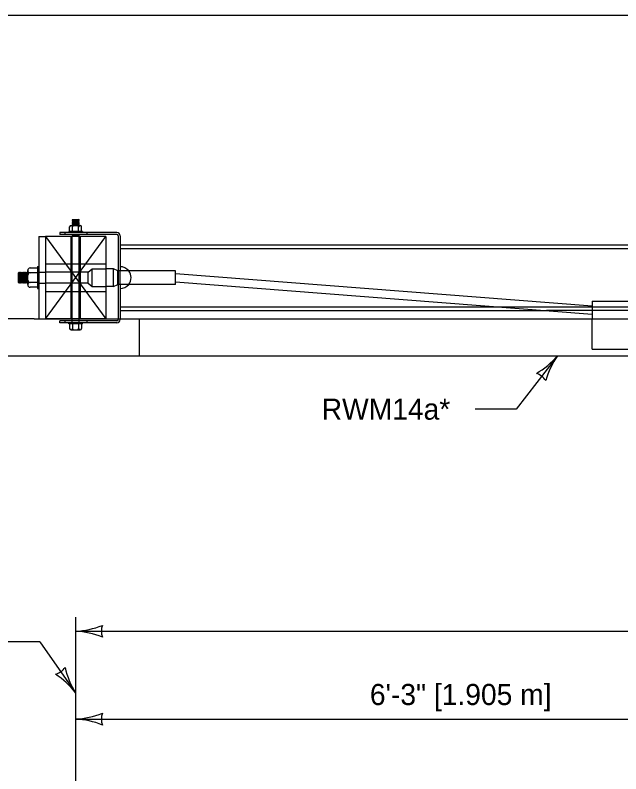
# Model space of a CAD drawing. Extents: x 49991.4 to 50021, y 49987.6 to 50011.4.
# Drawn here: x 50001.173 to 50002.896, y 49996.841 to 49998.999 of the extents above; entities that cross this region are included whole.
import ezdxf

# ---------------------------------------------------------------- set-up
doc = ezdxf.new("R2010")
doc.units = 0
for name, color, linetype in [('Level 1', 7, 'Continuous'), ('Level 2', 7, 'Continuous'), ('Level 3', 7, 'Continuous'), ('Level 4', 7, 'Continuous')]:
    doc.layers.add(name, color=color, linetype=linetype)

msp = doc.modelspace()

# ---------------------------------------------------------------- linework, layer by layer
at = {"layer": 'Level 1'}
for p, q in [((50001.3538, 49998.4176), (50001.3355, 49998.4166)), ((50001.3355, 49998.4166), (50001.3367, 49998.4176)), ((50001.3355, 49998.4166), (50001.3367, 49998.4156)), ((50001.3538, 49998.4156), (50001.3355, 49998.4147)), ((50001.3355, 49998.4147), (50001.3367, 49998.4156)), ((50001.3355, 49998.4147), (50001.3367, 49998.4137)), ((50001.3538, 49998.4137), (50001.3355, 49998.4128)), ((50001.3355, 49998.4128), (50001.3367, 49998.4137)), ((50001.3355, 49998.4128), (50001.3367, 49998.4118)), ((50001.3538, 49998.4118), (50001.3355, 49998.4109)), ((50001.3355, 49998.4109), (50001.3367, 49998.4118)), ((50001.3355, 49998.4109), (50001.3367, 49998.4099)), ((50001.3367, 49998.4176), (50001.3538, 49998.4176)), ((50001.355, 49998.4166), (50001.3367, 49998.4156)), ((50001.355, 49998.4147), (50001.3367, 49998.4137)), ((50001.355, 49998.4128), (50001.3367, 49998.4118)), ((50001.355, 49998.4109), (50001.3367, 49998.4099)), ((50001.3538, 49998.4176), (50001.355, 49998.4166)), ((50001.3538, 49998.4156), (50001.355, 49998.4166)), ((50001.3538, 49998.4156), (50001.355, 49998.4147)), ((50001.3538, 49998.4137), (50001.355, 49998.4147)), ((50001.3538, 49998.4137), (50001.355, 49998.4128)), ((50001.3538, 49998.4118), (50001.355, 49998.4128)), ((50001.3538, 49998.4118), (50001.355, 49998.4109)), ((50001.3538, 49998.4099), (50001.355, 49998.4109)), ((50001.3282, 49998.384), (50001.3282, 49998.3969)), ((50001.3324, 49998.401), (50001.3581, 49998.401)), ((50001.3538, 49998.4099), (50001.3355, 49998.409)), ((50001.3355, 49998.409), (50001.3367, 49998.4099)), ((50001.3355, 49998.409), (50001.3367, 49998.408)), ((50001.3538, 49998.408), (50001.3355, 49998.407)), ((50001.3355, 49998.407), (50001.3367, 49998.408)), ((50001.3355, 49998.407), (50001.3367, 49998.406)), ((50001.3538, 49998.406), (50001.3355, 49998.4051)), ((50001.3355, 49998.4051), (50001.3367, 49998.406)), ((50001.3355, 49998.4051), (50001.3367, 49998.4042)), ((50001.3538, 49998.4042), (50001.3355, 49998.4032)), ((50001.3355, 49998.4032), (50001.3367, 49998.4042)), ((50001.3355, 49998.4032), (50001.3367, 49998.4022)), ((50001.3538, 49998.4022), (50001.3355, 49998.4013)), ((50001.3355, 49998.4013), (50001.3367, 49998.4022)), ((50001.3355, 49998.4013), (50001.3358, 49998.401)), ((50001.355, 49998.409), (50001.3367, 49998.408)), ((50001.355, 49998.407), (50001.3367, 49998.406)), ((50001.355, 49998.4051), (50001.3367, 49998.4042)), ((50001.355, 49998.4032), (50001.3367, 49998.4022)), ((50001.3367, 49998.384), (50001.3367, 49998.3969)), ((50001.355, 49998.4013), (50001.3518, 49998.401)), ((50001.3537, 49998.384), (50001.3537, 49998.3969)), ((50001.3538, 49998.4099), (50001.355, 49998.409)), ((50001.3538, 49998.408), (50001.355, 49998.409)), ((50001.3538, 49998.408), (50001.355, 49998.407)), ((50001.3538, 49998.406), (50001.355, 49998.407)), ((50001.3538, 49998.406), (50001.355, 49998.4051)), ((50001.3538, 49998.4042), (50001.355, 49998.4051)), ((50001.3538, 49998.4042), (50001.355, 49998.4032)), ((50001.3538, 49998.4022), (50001.355, 49998.4032)), ((50001.3538, 49998.4022), (50001.355, 49998.4013)), ((50001.3546, 49998.401), (50001.355, 49998.4013)), ((50001.3622, 49998.384), (50001.3622, 49998.3969)), ((50001.2411, 49998.3698), (50001.2411, 49998.1354)), ((50001.2411, 49998.3698), (50001.2594, 49998.3698)), ((50001.2594, 49998.1354), (50001.431, 49998.3698)), ((50001.2594, 49998.3698), (50001.431, 49998.1354)), ((50001.2594, 49998.3698), (50001.2594, 49998.1354)), ((50001.431, 49998.3698), (50001.2594, 49998.3698)), ((50001.2594, 49998.3698), (50001.2594, 49998.1354)), ((50001.4622, 49998.3813), (50001.3003, 49998.3813)), ((50001.3003, 49998.3813), (50001.3003, 49998.3754)), ((50001.4622, 49998.3754), (50001.3003, 49998.3754)), ((50001.3647, 49998.384), (50001.3257, 49998.384)), ((50001.3257, 49998.384), (50001.3257, 49998.3813)), ((50001.3349, 49998.384), (50001.3349, 49998.3813)), ((50001.3538, 49998.3754), (50001.3355, 49998.3745)), ((50001.3355, 49998.3745), (50001.3367, 49998.3754)), ((50001.3355, 49998.3745), (50001.3367, 49998.3735)), ((50001.3538, 49998.3735), (50001.3355, 49998.3726)), ((50001.3355, 49998.3726), (50001.3367, 49998.3735)), ((50001.3355, 49998.3726), (50001.3367, 49998.3716)), ((50001.3538, 49998.3716), (50001.3355, 49998.3707)), ((50001.3355, 49998.3707), (50001.3367, 49998.3716)), ((50001.3355, 49998.3707), (50001.3366, 49998.3698)), ((50001.3367, 49998.3754), (50001.3538, 49998.3754)), ((50001.355, 49998.3745), (50001.3367, 49998.3735)), ((50001.355, 49998.3726), (50001.3367, 49998.3716)), ((50001.355, 49998.3707), (50001.3383, 49998.3698)), ((50001.3538, 49998.3754), (50001.355, 49998.3745)), ((50001.3538, 49998.3735), (50001.355, 49998.3745)), ((50001.3538, 49998.3735), (50001.355, 49998.3726)), ((50001.3538, 49998.3716), (50001.355, 49998.3726)), ((50001.3538, 49998.3716), (50001.355, 49998.3707)), ((50001.3539, 49998.3698), (50001.355, 49998.3707)), ((50001.3556, 49998.384), (50001.3556, 49998.3813)), ((50001.3647, 49998.384), (50001.3647, 49998.3813)), ((50001.431, 49998.3698), (50001.431, 49998.1354)), ((50001.4661, 49998.3715), (50001.4661, 49998.2721)), ((50001.4719, 49998.3715), (50001.4719, 49998.2721)), ((50001.4719, 49998.3462), (50003.5623, 49998.3462)), ((50001.4719, 49998.3462), (50001.4719, 49998.2838)), ((50001.2367, 49998.2839), (50001.2367, 49998.2214)), ((50001.2367, 49998.2839), (50001.2411, 49998.2839)), ((50001.1829, 49998.2664), (50001.1844, 49998.2683)), ((50001.1829, 49998.2664), (50001.1844, 49998.237)), ((50001.1829, 49998.239), (50001.1829, 49998.2664)), ((50001.1844, 49998.2683), (50001.186, 49998.239)), ((50001.186, 49998.2664), (50001.1844, 49998.2683)), ((50001.186, 49998.2664), (50001.1875, 49998.2683)), ((50001.186, 49998.2664), (50001.1875, 49998.237)), ((50001.189, 49998.2664), (50001.1875, 49998.2683)), ((50001.1875, 49998.2683), (50001.189, 49998.239)), ((50001.189, 49998.2664), (50001.1905, 49998.2683)), ((50001.189, 49998.2664), (50001.1905, 49998.237)), ((50001.1921, 49998.2664), (50001.1905, 49998.2683)), ((50001.1905, 49998.2683), (50001.1921, 49998.239)), ((50001.1921, 49998.2664), (50001.1936, 49998.2683)), ((50001.1921, 49998.2664), (50001.1936, 49998.237)), ((50001.1952, 49998.2664), (50001.1936, 49998.2683)), ((50001.1936, 49998.2683), (50001.1952, 49998.239)), ((50001.1952, 49998.2664), (50001.1967, 49998.2683)), ((50001.1952, 49998.2664), (50001.1967, 49998.237)), ((50001.1983, 49998.2664), (50001.1967, 49998.2683)), ((50001.1967, 49998.2683), (50001.1983, 49998.239)), ((50001.1983, 49998.2664), (50001.1998, 49998.2683)), ((50001.1983, 49998.2664), (50001.1998, 49998.237)), ((50001.2013, 49998.2664), (50001.1998, 49998.2683)), ((50001.1998, 49998.2683), (50001.2013, 49998.239)), ((50001.2013, 49998.2664), (50001.2028, 49998.2683)), ((50001.2013, 49998.2664), (50001.2028, 49998.237)), ((50001.2044, 49998.2664), (50001.2028, 49998.2683)), ((50001.2028, 49998.2683), (50001.2044, 49998.239)), ((50001.2044, 49998.2664), (50001.2059, 49998.2683)), ((50001.2044, 49998.2664), (50001.2059, 49998.237)), ((50001.2075, 49998.2664), (50001.2059, 49998.2683)), ((50001.2059, 49998.2683), (50001.2075, 49998.239)), ((50001.2075, 49998.2664), (50001.209, 49998.2683)), ((50001.2075, 49998.2664), (50001.209, 49998.237)), ((50001.209, 49998.2683), (50001.2094, 49998.26)), ((50001.2094, 49998.2678), (50001.209, 49998.2683)), ((50001.2094, 49998.2327), (50001.2094, 49998.2727)), ((50001.2367, 49998.28), (50001.2161, 49998.28)), ((50001.2367, 49998.2663), (50001.2161, 49998.2663)), ((50001.2367, 49998.2693), (50001.2411, 49998.2693)), ((50001.4535, 49998.278), (50001.431, 49998.278)), ((50001.4535, 49998.2272), (50001.4535, 49998.278)), ((50001.4652, 49998.2721), (50001.4535, 49998.278)), ((50001.4652, 49998.2331), (50001.4652, 49998.2721)), ((50001.6293, 49998.2721), (50001.4652, 49998.2721)), ((50001.6293, 49998.2331), (50001.6293, 49998.2721)), ((50001.6293, 49998.2644), (50002.814, 49998.1725)), ((50001.1844, 49998.237), (50001.1829, 49998.239)), ((50001.1844, 49998.237), (50001.186, 49998.239)), ((50001.1875, 49998.237), (50001.186, 49998.239)), ((50001.1875, 49998.237), (50001.189, 49998.239)), ((50001.1905, 49998.237), (50001.189, 49998.239)), ((50001.1905, 49998.237), (50001.1921, 49998.239)), ((50001.1936, 49998.237), (50001.1921, 49998.239)), ((50001.1936, 49998.237), (50001.1952, 49998.239)), ((50001.1967, 49998.237), (50001.1952, 49998.239)), ((50001.1967, 49998.237), (50001.1983, 49998.239)), ((50001.1998, 49998.237), (50001.1983, 49998.239)), ((50001.1998, 49998.237), (50001.2013, 49998.239)), ((50001.2028, 49998.237), (50001.2013, 49998.239)), ((50001.2028, 49998.237), (50001.2044, 49998.239)), ((50001.2059, 49998.237), (50001.2044, 49998.239)), ((50001.2059, 49998.237), (50001.2075, 49998.239)), ((50001.209, 49998.237), (50001.2075, 49998.239)), ((50001.2094, 49998.2378), (50001.209, 49998.237)), ((50001.2367, 49998.239), (50001.2161, 49998.239)), ((50001.6293, 49998.2408), (50002.814, 49998.149)), ((50001.2367, 49998.2253), (50001.2161, 49998.2253)), ((50001.2367, 49998.2361), (50001.2411, 49998.2361)), ((50001.2367, 49998.2214), (50001.2411, 49998.2214)), ((50001.4535, 49998.2272), (50001.431, 49998.2272)), ((50001.4535, 49998.2272), (50001.4652, 49998.2331)), ((50001.6293, 49998.2331), (50001.4652, 49998.2331)), ((50001.4661, 49998.2331), (50001.4661, 49998.1354)), ((50001.4719, 49998.2331), (50001.4719, 49998.1354)), ((50001.4719, 49998.2214), (50001.4719, 49998.159)), ((50002.814, 49998.1861), (50003.314, 49998.1861)), ((50002.814, 49998.1861), (50002.814, 49998.1354)), ((50001.4719, 49998.159), (50002.6846, 49998.159)), ((50001.2278, 49998.1354), (50001.1186, 49998.1356)), ((50001.2278, 49998.1354), (50006.4114, 49998.1354)), ((50001.2411, 49998.1354), (50001.2594, 49998.1354)), ((50001.431, 49998.1354), (50001.2594, 49998.1354)), ((50001.118, 49998.0301), (50001.5093, 49998.0301)), ((50001.5093, 49998.0301), (50006.4114, 49998.0301))]:
    msp.add_line(p, q, dxfattribs=at)
msp.add_lwpolyline([(49999.3835, 49998.9992), (50016.7501, 49998.9992), (50016.7501, 49987.7988), (49999.3835, 49987.7988)], close=True, dxfattribs=at)
for centre, radius, start, end in [((50001.3324, 49998.3968), 0.0042, 89.5221, 179.5221), ((50001.3325, 49998.3968), 0.00423, 0.896, 90.896), ((50001.3409, 49998.3968), 0.0042, 92.0518, 179.5951), ((50001.3495, 49998.3969), 0.00418, 0.0618, 87.1409), ((50001.358, 49998.3968), 0.00426, 88.7945, 178.7945), ((50001.3581, 49998.3969), 0.00418, 0.1602, 90.1602), ((50001.4622, 49998.3715), 0.00975, 0, 90), ((50001.4622, 49998.3715), 0.0039, 0, 90), ((50001.4719, 49998.2526), 0.0312, 38.6822, 90), ((50001.2161, 49998.2733), 0.00675, 90, 181.5911), ((50001.2161, 49998.2731), 0.00675, 180, 270), ((50001.2161, 49998.2596), 0.00675, 90, 176.5125), ((50001.2161, 49998.2458), 0.00675, 183.4875, 270), ((50001.2161, 49998.2323), 0.00675, 90, 180.5728), ((50001.2161, 49998.2321), 0.00675, 178.9813, 270), ((50001.4719, 49998.2526), 0.0312, 270, 321.3178)]:
    msp.add_arc(centre, radius, start, end, dxfattribs=at)
at = {"layer": 'Level 3'}
for p, q in [((50002.7156, 49998.0301), (50002.5979, 49997.8785)), ((50002.5979, 49997.8785), (50002.482, 49997.8785)), ((50001.3453, 49997.2867), (50001.3452, 49995.9948)), ((50001.3465, 49997.2468), (50006.0327, 49997.2468)), ((50001.244, 49997.2168), (50001.0991, 49997.2168)), ((50001.244, 49997.2168), (50001.3453, 49997.0717)), ((50001.3453, 49996.9968), (50003.689, 49996.9968))]:
    msp.add_line(p, q, dxfattribs=at)
for centre, radius, start, end in [((50002.5458, 49998.1736), 0.2223, 299.6177, 319.8012), ((50002.9065, 49997.8964), 0.233, 144.989, 164.2388), ((50002.637, 49997.9288), 0.0548, 34.3005, 70.0229), ((50001.3338, 49997.4795), 0.2331, 272.824, 292.0739), ((50001.3361, 49997.0245), 0.2224, 67.459, 87.6425), ((50001.4735, 49997.2467), 0.0548, 162.1388, 197.8612), ((50001.2719, 49997.1768), 0.0548, 287.0415, 322.7639), ((50001.5327, 49997.1912), 0.2223, 192.3587, 212.5422), ((50001.161, 49996.9291), 0.233, 37.73, 56.9799), ((50001.3338, 49997.2295), 0.233, 272.8273, 292.0772), ((50001.4735, 49996.9968), 0.0548, 162.1388, 197.8612), ((50001.3361, 49996.7747), 0.2223, 67.456, 87.6395)]:
    msp.add_arc(centre, radius, start, end, dxfattribs=at)
at = {"layer": 'Level 4'}
for p, q in [((50001.316, 49998.3754), (50001.316, 49998.3813)), ((50001.3316, 49998.3698), (50001.3316, 49998.1354)), ((50001.3355, 49998.1239), (50001.3355, 49998.3698)), ((50001.355, 49998.1239), (50001.355, 49998.3698)), ((50001.3589, 49998.1354), (50001.3589, 49998.3698)), ((50001.3783, 49998.3754), (50001.3783, 49998.3813)), ((50001.4719, 49998.3355), (50003.5623, 49998.3355)), ((50001.2594, 49998.2916), (50001.431, 49998.2916)), ((50001.2411, 49998.2682), (50001.2594, 49998.2682)), ((50001.3812, 49998.2682), (50001.2594, 49998.2682)), ((50001.3812, 49998.2682), (50001.3927, 49998.278)), ((50001.3812, 49998.237), (50001.3812, 49998.2682)), ((50001.3927, 49998.2272), (50001.3927, 49998.278)), ((50001.3927, 49998.278), (50001.431, 49998.278)), ((50001.4661, 49998.2721), (50001.4661, 49998.2331)), ((50001.4719, 49998.2331), (50001.4719, 49998.2721)), ((50001.2411, 49998.237), (50001.2594, 49998.237)), ((50001.3812, 49998.237), (50001.2594, 49998.237)), ((50001.3812, 49998.237), (50001.3927, 49998.2272)), ((50001.3927, 49998.2272), (50001.431, 49998.2272)), ((50001.2594, 49998.2136), (50001.431, 49998.2136)), ((50001.4719, 49998.1697), (50003.5623, 49998.1697)), ((50003.3839, 49998.159), (50002.6846, 49998.159)), ((50001.4622, 49998.1297), (50001.3003, 49998.1297)), ((50001.3003, 49998.1239), (50001.3003, 49998.1297)), ((50001.316, 49998.1239), (50001.316, 49998.1297)), ((50001.3783, 49998.1239), (50001.3783, 49998.1297)), ((50001.4661, 49998.1354), (50001.4661, 49998.1336)), ((50001.4719, 49998.1336), (50001.4719, 49998.1354)), ((50001.5262, 49998.1354), (50001.5262, 49998.0301)), ((50002.814, 49998.049), (50002.814, 49998.1354)), ((50001.4622, 49998.1239), (50001.3003, 49998.1239)), ((50001.3257, 49998.1212), (50001.3257, 49998.1239)), ((50001.3647, 49998.1212), (50001.3257, 49998.1212)), ((50001.3282, 49998.1212), (50001.3282, 49998.1083)), ((50001.3349, 49998.1212), (50001.3349, 49998.1239)), ((50001.3367, 49998.1212), (50001.3367, 49998.1083)), ((50001.3537, 49998.1212), (50001.3537, 49998.1083)), ((50001.3556, 49998.1212), (50001.3556, 49998.1239)), ((50001.3622, 49998.1212), (50001.3622, 49998.1083)), ((50001.3647, 49998.1212), (50001.3647, 49998.1239)), ((50001.3324, 49998.1042), (50001.3581, 49998.1042)), ((50002.814, 49998.049), (50003.314, 49998.049))]:
    msp.add_line(p, q, dxfattribs=at)
for centre, radius, start, end in [((50001.4719, 49998.2526), 0.0312, 321.3178, 38.6822), ((50001.4622, 49998.1336), 0.00975, 270, 0), ((50001.4622, 49998.1336), 0.0039, 270, 0), ((50001.3324, 49998.1084), 0.0042, 180.4779, 270.4779), ((50001.3325, 49998.1084), 0.00423, 269.104, 359.104), ((50001.3409, 49998.1084), 0.0042, 180.4049, 267.9482), ((50001.3495, 49998.1083), 0.00418, 272.8591, 359.9382), ((50001.358, 49998.1084), 0.00426, 181.2055, 271.2055), ((50001.3581, 49998.1083), 0.00418, 269.8398, 359.8398)]:
    msp.add_arc(centre, radius, start, end, dxfattribs=at)

# ---------------------------------------------------------------- texts
at = {"layer": 'Level 2'}
for s, p in [('RWM14a*', (50002.0452, 49997.8485)), ('6\'-3" [1.905 m]', (50002.1822, 49997.0368))]:
    msp.add_text(s, height=0.06, dxfattribs=at).set_placement(p)

doc.saveas('drawing.dxf')
